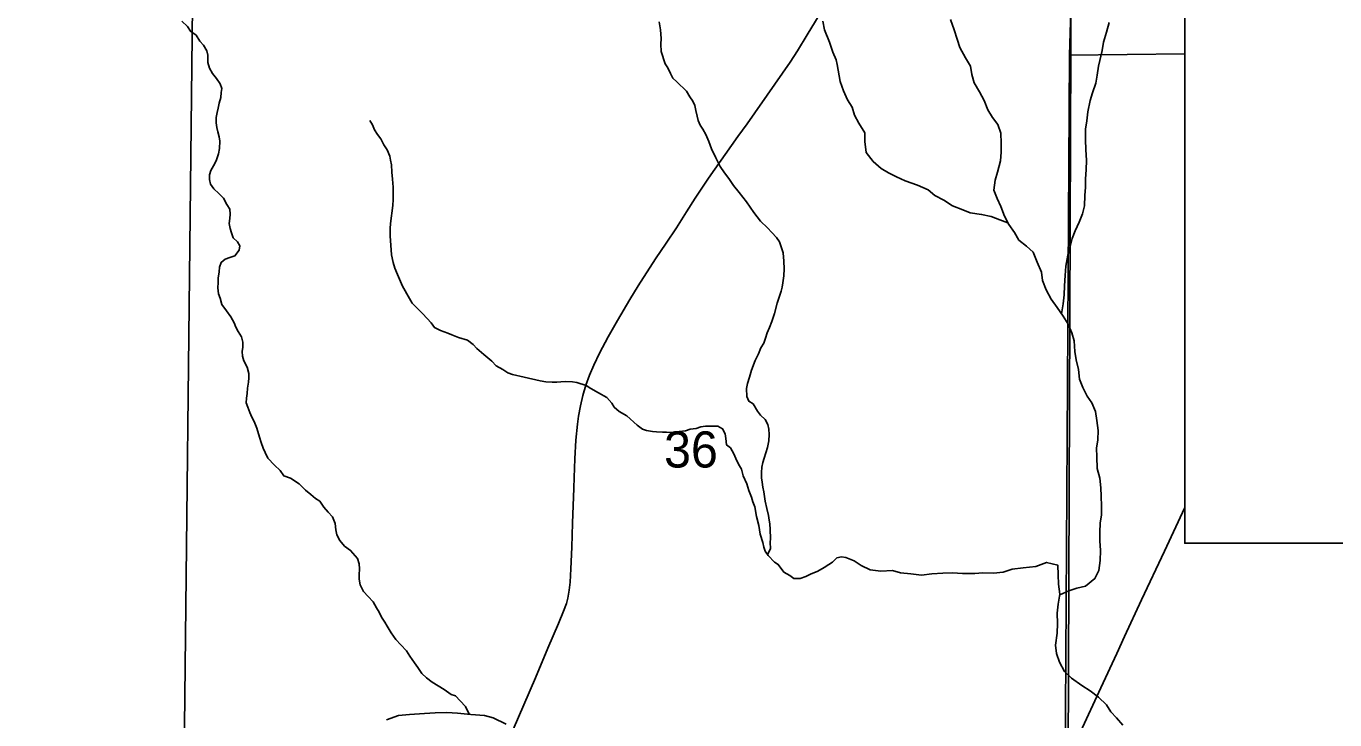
# Model space of a CAD drawing. Extents: x 0 to 34, y 0 to 22.
# Drawn here: x 4.435 to 5.951, y 16.058 to 16.861 of the extents above; entities that cross this region are included whole.
import ezdxf

# ---------------------------------------------------------------- set-up
doc = ezdxf.new("R2010")
doc.units = 0
for name, color, linetype in [('GM_X_County_Road', 7, 'Continuous'), ('GM_X_Minor_River', 7, 'Continuous'), ('GM_X_Section', 7, 'Continuous'), ('GM_X_Section_Text', 7, 'Continuous'), ('GM_X_State_Route', 7, 'Continuous'), ('SH_Text', 7, 'Continuous')]:
    doc.layers.add(name, color=color, linetype=linetype)

msp = doc.modelspace()

# ---------------------------------------------------------------- linework, layer by layer
at = {"layer": 'GM_X_County_Road'}
msp.add_lwpolyline([(4.9932, 16.0325), (5.0117, 16.0754), (5.0254, 16.1068), (5.0395, 16.141), (5.052, 16.1697), (5.0578, 16.1838), (5.0611, 16.1927), (5.0627, 16.199), (5.0644, 16.2082), (5.0655, 16.2175), (5.0665, 16.2331), (5.0674, 16.258), (5.0682, 16.2859), (5.0696, 16.3262), (5.0702, 16.3386), (5.0709, 16.3602), (5.0722, 16.3819), (5.0741, 16.4004), (5.0753, 16.4096), (5.0775, 16.4217), (5.0803, 16.4338), (5.0838, 16.4456), (5.0879, 16.4573), (5.0928, 16.4687), (5.0996, 16.4826), (5.1097, 16.5018), (5.1204, 16.5207), (5.1345, 16.5448), (5.1441, 16.5607), (5.1645, 16.5919), (5.1766, 16.61), (5.1887, 16.628), (5.2003, 16.6465), (5.2102, 16.6622), (5.2259, 16.6854), (5.2598, 16.7336), (5.2705, 16.7484), (5.2795, 16.761), (5.2937, 16.7814), (5.3202, 16.8197), (5.3287, 16.8327), (5.3401, 16.8512), (5.3592, 16.8832)], dxfattribs=at)
at = {"layer": 'GM_X_Minor_River'}
for points in [[(4.6603, 16.7948), (4.6561, 16.8009), (4.6511, 16.8066), (4.6477, 16.8126), (4.6457, 16.8195), (4.6457, 16.8279), (4.6446, 16.8328), (4.6407, 16.8393), (4.6365, 16.8442), (4.6323, 16.8511), (4.6258, 16.8556), (4.6224, 16.861), (4.6159, 16.8674)], [(5.2942, 16.2491), (5.2974, 16.2567), (5.2973, 16.2636), (5.2977, 16.2681), (5.2973, 16.2784), (5.2969, 16.2849), (5.2961, 16.2894), (5.2954, 16.2947), (5.2934, 16.3027), (5.2915, 16.3115), (5.29, 16.3221), (5.2888, 16.3274), (5.288, 16.3335), (5.2872, 16.3385), (5.2872, 16.3446), (5.2876, 16.3506), (5.2887, 16.356), (5.2902, 16.3613), (5.294, 16.3735), (5.2955, 16.3814), (5.2959, 16.3887), (5.2955, 16.3948), (5.2944, 16.4001), (5.2913, 16.4058), (5.2859, 16.4111), (5.2825, 16.4157), (5.2775, 16.424), (5.2725, 16.4271), (5.2702, 16.4324), (5.2698, 16.4419), (5.271, 16.4476), (5.2732, 16.4548), (5.2755, 16.4632), (5.2797, 16.4742), (5.2835, 16.4818), (5.2865, 16.4891), (5.2899, 16.4944), (5.2918, 16.5001), (5.2937, 16.5062), (5.2964, 16.5123), (5.299, 16.5195), (5.3021, 16.5286), (5.3051, 16.5408), (5.3081, 16.5488), (5.31, 16.5545), (5.3112, 16.559), (5.3119, 16.564), (5.313, 16.5723), (5.3134, 16.5803), (5.313, 16.5891), (5.3122, 16.5989), (5.308, 16.6115), (5.3045, 16.6168), (5.2992, 16.6225), (5.2942, 16.6279), (5.2858, 16.6355), (5.2781, 16.6457), (5.2697, 16.6579), (5.2613, 16.6689), (5.2548, 16.6769), (5.2494, 16.6849), (5.2441, 16.6914), (5.2391, 16.699), (5.2341, 16.7089), (5.2291, 16.7195), (5.226, 16.7279), (5.2226, 16.7359), (5.2191, 16.742), (5.2161, 16.7469), (5.2138, 16.7522), (5.2126, 16.7572), (5.2111, 16.7637), (5.2099, 16.7694), (5.2076, 16.7747), (5.2042, 16.7796), (5.2003, 16.7861), (5.1892, 16.7971), (5.1843, 16.8013), (5.1816, 16.8066), (5.1785, 16.8131), (5.1754, 16.8177), (5.1708, 16.8321), (5.1704, 16.8405), (5.1708, 16.847), (5.17, 16.8572), (5.1685, 16.8664)], [(5.3782, 16.7972), (5.3747, 16.8172), (5.3735, 16.8225), (5.3697, 16.8313), (5.3658, 16.843), (5.3601, 16.8571), (5.3581, 16.8674)], [(5.6326, 16.2027), (5.6429, 16.2074), (5.6524, 16.2104), (5.6623, 16.213), (5.6733, 16.2217), (5.6778, 16.2311), (5.6794, 16.2425), (5.6798, 16.2543), (5.6791, 16.2653), (5.6791, 16.2755), (5.6792, 16.2858), (5.6811, 16.2956), (5.6808, 16.3055), (5.6804, 16.3172), (5.6801, 16.3267), (5.679, 16.3381), (5.676, 16.3491), (5.6757, 16.3628), (5.6753, 16.3727), (5.6765, 16.3825), (5.6769, 16.3932), (5.6755, 16.4049), (5.674, 16.4152), (5.6699, 16.4254), (5.6642, 16.4331), (5.6593, 16.4429), (5.6556, 16.4528), (5.6541, 16.4638), (5.6515, 16.4749), (5.6501, 16.4847), (5.6493, 16.4969), (5.6464, 16.5064), (5.6422, 16.5163), (5.6366, 16.5254), (5.6295, 16.5357), (5.6227, 16.5452), (5.6167, 16.5562), (5.6126, 16.5669), (5.6115, 16.5764), (5.6066, 16.5881), (5.6017, 16.5996), (5.5942, 16.6068), (5.5851, 16.6137), (5.5802, 16.6224), (5.5735, 16.6319), (5.5686, 16.6414), (5.5645, 16.6525), (5.56, 16.662), (5.5562, 16.6715), (5.5578, 16.6829), (5.5605, 16.6923), (5.5639, 16.7056), (5.5647, 16.7155), (5.5648, 16.7261), (5.5644, 16.7375), (5.5607, 16.7477), (5.5547, 16.7557), (5.5494, 16.7645), (5.5449, 16.7755), (5.5397, 16.7854), (5.5336, 16.7957), (5.5307, 16.8056), (5.5292, 16.815), (5.5235, 16.8249), (5.5168, 16.8367), (5.5138, 16.8462), (5.5104, 16.8573), (5.5059, 16.869)], [(5.6346, 16.5282), (5.6367, 16.5398), (5.6378, 16.5501), (5.6379, 16.5607), (5.639, 16.5728), (5.6398, 16.5834), (5.6418, 16.5963), (5.6445, 16.6062), (5.6468, 16.6156), (5.6506, 16.6244), (5.6552, 16.6346), (5.659, 16.644), (5.6613, 16.6535), (5.6617, 16.6653), (5.6625, 16.6748), (5.6625, 16.6843), (5.663, 16.6953), (5.6634, 16.7059), (5.6627, 16.7184), (5.6623, 16.7298), (5.6624, 16.7423), (5.6639, 16.7518), (5.6651, 16.7624), (5.6678, 16.7753), (5.6705, 16.7844), (5.6743, 16.7954), (5.6759, 16.8048), (5.6774, 16.8151), (5.6816, 16.8333), (5.6832, 16.8428), (5.6866, 16.8545), (5.6897, 16.8655)], [(4.8262, 16.2068), (4.8223, 16.2144), (4.8212, 16.2209), (4.8212, 16.2262), (4.8215, 16.233), (4.8211, 16.2387), (4.8192, 16.2448), (4.8112, 16.2543), (4.8043, 16.2593), (4.7989, 16.2657), (4.7951, 16.2722), (4.7943, 16.2783), (4.7932, 16.2855), (4.7901, 16.2931), (4.7851, 16.2985), (4.7801, 16.3042), (4.7756, 16.3114), (4.7706, 16.3144), (4.7652, 16.319), (4.7591, 16.3239), (4.7515, 16.3316), (4.7415, 16.338), (4.7339, 16.3407), (4.7297, 16.3468), (4.7232, 16.3529), (4.7155, 16.3612), (4.7124, 16.3677), (4.7101, 16.3726), (4.7078, 16.3791), (4.7059, 16.3856), (4.7025, 16.3958), (4.6994, 16.4035), (4.6967, 16.4088), (4.6944, 16.4141), (4.6921, 16.4202), (4.6902, 16.4251), (4.6905, 16.4308), (4.6913, 16.4362), (4.6917, 16.4422), (4.6928, 16.4491), (4.6932, 16.454), (4.6932, 16.459), (4.6916, 16.4666), (4.6874, 16.4738), (4.6859, 16.4791), (4.6855, 16.4845), (4.6866, 16.4898), (4.6866, 16.4955), (4.685, 16.5016), (4.6812, 16.5077), (4.6785, 16.513), (4.6762, 16.5179), (4.6724, 16.5248), (4.6674, 16.5316), (4.662, 16.5392), (4.6601, 16.5465), (4.6582, 16.5514), (4.6574, 16.5582), (4.6578, 16.5647), (4.6578, 16.5697), (4.6589, 16.5769), (4.6593, 16.5822), (4.6612, 16.5879), (4.6661, 16.5917), (4.6715, 16.5936), (4.6772, 16.5955), (4.6821, 16.602), (4.6829, 16.6069), (4.6802, 16.6118), (4.6752, 16.6164), (4.6733, 16.6221), (4.6718, 16.6271), (4.6706, 16.6328), (4.6714, 16.6385), (4.6717, 16.6438), (4.6713, 16.6495), (4.6679, 16.6548), (4.664, 16.6621), (4.6587, 16.6678), (4.653, 16.6731), (4.6491, 16.6784), (4.648, 16.6837), (4.648, 16.6894), (4.6495, 16.6944), (4.6525, 16.6997), (4.6555, 16.7054), (4.6582, 16.7134), (4.6593, 16.7199), (4.6597, 16.7282), (4.6589, 16.7332), (4.6574, 16.7392), (4.6562, 16.7442), (4.6554, 16.7495), (4.6554, 16.7556), (4.6566, 16.7613), (4.6577, 16.7666), (4.6592, 16.7723), (4.6611, 16.7788), (4.6615, 16.7845), (4.6622, 16.7894), (4.6603, 16.7948)], [(5.5726, 16.6336), (5.5633, 16.6373), (5.5531, 16.6411), (5.5421, 16.6435), (5.5289, 16.6451), (5.5202, 16.6489), (5.5085, 16.6535), (5.4983, 16.66), (5.4878, 16.6654), (5.4802, 16.6719), (5.4678, 16.6772), (5.4534, 16.6822), (5.4436, 16.6868), (5.4342, 16.6914), (5.4259, 16.6964), (5.4165, 16.7048), (5.4082, 16.7151), (5.4067, 16.728), (5.4067, 16.7379), (5.4, 16.7489), (5.3947, 16.7584), (5.3921, 16.7675), (5.3869, 16.7763), (5.382, 16.7865), (5.3782, 16.7972)], [(4.8606, 16.6749), (4.8598, 16.6844), (4.859, 16.6924), (4.8586, 16.7007), (4.8574, 16.7064), (4.8567, 16.711), (4.8536, 16.7182), (4.8498, 16.7239), (4.8463, 16.7308), (4.8425, 16.7361), (4.839, 16.7414), (4.8367, 16.7471), (4.8337, 16.7521)], [(5.3848, 16.2462), (5.3798, 16.2468), (5.3745, 16.2456), (5.3695, 16.2407), (5.365, 16.238), (5.3596, 16.2346), (5.3524, 16.2301), (5.344, 16.2267), (5.3383, 16.224), (5.3318, 16.2217), (5.3245, 16.2217), (5.32, 16.2251), (5.3131, 16.2293), (5.3066, 16.2381), (5.302, 16.2407), (5.2947, 16.2484), (5.2913, 16.2533), (5.2897, 16.2582), (5.2886, 16.2636), (5.2855, 16.2731), (5.2839, 16.283), (5.2812, 16.2936), (5.2793, 16.3046), (5.277, 16.3107), (5.2755, 16.3161), (5.2724, 16.3237), (5.2701, 16.3313), (5.2659, 16.3408), (5.2639, 16.3484), (5.2605, 16.3541), (5.2574, 16.3606), (5.2551, 16.3663), (5.2513, 16.3731), (5.2467, 16.3765), (5.2459, 16.3841), (5.2451, 16.3895), (5.2421, 16.3952), (5.2367, 16.3982), (5.2222, 16.3982), (5.2169, 16.3975), (5.2116, 16.3956), (5.2047, 16.3948), (5.1993, 16.3929), (5.1883, 16.3918), (5.1826, 16.391), (5.1772, 16.3914), (5.1726, 16.3914), (5.1654, 16.3918), (5.1608, 16.3922), (5.1539, 16.3933), (5.1493, 16.3948), (5.1432, 16.3994), (5.131, 16.4101), (5.1222, 16.415), (5.1165, 16.4203), (5.1138, 16.4249), (5.108, 16.4314), (5.0985, 16.4367), (5.0893, 16.442), (5.084, 16.4451), (5.0733, 16.4489), (5.0683, 16.4496), (5.0599, 16.45), (5.0546, 16.4496), (5.05, 16.4493), (5.0447, 16.4493), (5.0374, 16.4497), (5.0309, 16.4508), (5.0122, 16.455), (4.9988, 16.458), (4.9935, 16.4599), (4.9874, 16.4638), (4.9797, 16.4679), (4.9748, 16.4736), (4.9656, 16.4813), (4.9576, 16.4881), (4.953, 16.4927), (4.9468, 16.4976), (4.9361, 16.501), (4.9285, 16.5041), (4.9239, 16.506), (4.9155, 16.509), (4.9083, 16.5125), (4.9044, 16.5178), (4.8949, 16.5281), (4.8826, 16.5406), (4.8796, 16.5459), (4.8715, 16.5604), (4.8654, 16.5737), (4.8623, 16.5813), (4.8604, 16.5878), (4.8585, 16.5965), (4.858, 16.6079), (4.8569, 16.6182), (4.8572, 16.6273), (4.8576, 16.6327), (4.8584, 16.6391), (4.8595, 16.6475), (4.8602, 16.6543), (4.8606, 16.6604), (4.8606, 16.6749)], [(5.6678, 16.0915), (5.658, 16.098), (5.646, 16.1064), (5.6381, 16.1141), (5.6324, 16.1247), (5.6287, 16.135), (5.6276, 16.1445), (5.6295, 16.1585), (5.6299, 16.1695), (5.6296, 16.1817), (5.6308, 16.1919), (5.6327, 16.2036), (5.6313, 16.2154), (5.6309, 16.226), (5.6302, 16.2374), (5.6174, 16.2405), (5.6049, 16.2357), (5.5901, 16.2342), (5.5776, 16.2324), (5.567, 16.229), (5.5557, 16.2279), (5.5436, 16.2284), (5.5341, 16.2276), (5.5201, 16.2277), (5.5084, 16.2282), (5.4971, 16.2278), (5.4846, 16.2271), (5.4725, 16.2257), (5.46, 16.2272), (5.4483, 16.2284), (5.4388, 16.2311), (5.4252, 16.2301), (5.4131, 16.2317), (5.4026, 16.237), (5.3943, 16.2424), (5.3848, 16.2462)], [(4.9486, 16.0646), (4.9444, 16.0736), (4.9383, 16.0801), (4.9326, 16.0858), (4.9276, 16.0873), (4.9196, 16.0934), (4.9058, 16.1018), (4.8993, 16.1067), (4.8936, 16.1117), (4.889, 16.1189), (4.8851, 16.1242), (4.8798, 16.1318), (4.8759, 16.1379), (4.8694, 16.1448), (4.8637, 16.1512), (4.8583, 16.1589), (4.8534, 16.1665), (4.8507, 16.1714), (4.8472, 16.1771), (4.8442, 16.1828), (4.8411, 16.1878), (4.8373, 16.1946), (4.8315, 16.2011), (4.8262, 16.2068)], [(5.7055, 16.0519), (5.6983, 16.0603), (5.6919, 16.0675), (5.6867, 16.0755), (5.6776, 16.0843), (5.6678, 16.0915)], [(4.8529, 16.058), (4.8669, 16.063), (4.8794, 16.0642), (4.8968, 16.0654), (4.9093, 16.0662), (4.9226, 16.0666), (4.9351, 16.0659), (4.9503, 16.0644), (4.9662, 16.0633), (4.9764, 16.0603), (4.9916, 16.0532)]]:
    msp.add_lwpolyline(points, dxfattribs=at)
at = {"layer": 'GM_X_Section'}
for points in [[(6.8036, 16.9797), (6.7979, 17.8558), (5.6465, 17.841), (5.6459, 16.8927), (5.644, 16.8278), (5.7774, 16.8294), (5.7774, 16.9797)], [(3.6155, 16.8848), (4.6282, 16.8848), (4.6171, 15.8766), (3.6166, 15.8725), (3.6011, 15.8725)], [(5.6459, 16.8927), (5.644, 16.8278), (5.6379, 15.8781), (4.6171, 15.8766), (4.6282, 16.8848)], [(5.7774, 16.8294), (5.644, 16.8278), (5.6379, 15.8781), (6.7969, 15.8732), (6.8, 16.2626), (5.7774, 16.2626)]]:
    msp.add_lwpolyline(points, close=True, dxfattribs=at)
at = {"layer": 'GM_X_State_Route'}
for points in [[(5.6474, 17.3472), (5.6423, 16.0151), (5.6416, 15.8841), (6.7968, 15.8774), (7.8024, 15.8725), (7.8042, 16.2626), (5.7774, 16.2626), (5.7774, 16.9797)], [(5.6423, 16.0151), (5.6474, 17.3472)], [(5.6426, 16.0146), (5.6565, 16.0444), (5.68, 16.0953), (5.6985, 16.1348), (5.7076, 16.1546), (5.7274, 16.1969), (5.7537, 16.2533), (5.7774, 16.304)]]:
    msp.add_lwpolyline(points, dxfattribs=at)
at = {"layer": 'SH_Text'}
msp.add_lwpolyline([(5.7774, 16.9797), (7.9972, 16.9797), (7.9972, 16.2626), (5.7774, 16.2626)], close=True, dxfattribs=at)

# ---------------------------------------------------------------- texts
at = {"layer": 'GM_X_Section_Text'}
msp.add_text('36', height=0.04186, rotation=0, dxfattribs=at).set_placement((5.1743, 16.3503))

doc.saveas('drawing.dxf')
